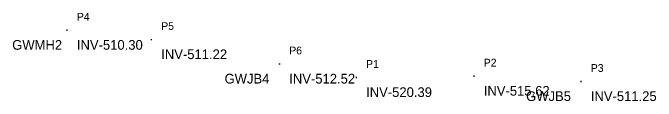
# Model space of a CAD drawing. Extents: x 1730979 to 1735363, y 649887 to 652110.
# Drawn here: x 1735032.4 to 1735362.8, y 649933.3 to 649978.8 of the extents above; entities that cross this region are included whole.
import ezdxf

# ---------------------------------------------------------------- set-up
doc = ezdxf.new("R2010")
doc.units = 0
for name, color, linetype in [('SURVEY - DRAINAGE - Storm Sewer - Points - Elevations', 7, 'Continuous'), ('SURVEY - DRAINAGE - Storm Sewer - Points - Locators', 7, 'Continuous'), ('SURVEY - DRAINAGE - Storm Sewer - Points - Numbers', 7, 'Continuous'), ('SURVEY - DRAINAGE - Storm Sewer Text', 7, 'Continuous')]:
    doc.layers.add(name, color=color, linetype=linetype)

msp = doc.modelspace()

# ---------------------------------------------------------------- linework, layer by layer
at = {"layer": 'SURVEY - DRAINAGE - Storm Sewer - Points - Locators'}
for p, q in [((1735060.58, 649969.75), (1735060.08, 649969.75)), ((1735060.33, 649969.5), (1735060.33, 649970)), ((1735060.33, 649969.75), (1735060.33, 649969.75)), ((1735060.33, 649969.75), (1735060.33, 649969.75)), ((1735103.88, 649964.94), (1735103.38, 649964.94)), ((1735103.63, 649964.69), (1735103.63, 649965.19)), ((1735103.63, 649964.94), (1735103.63, 649964.94)), ((1735103.63, 649964.94), (1735103.63, 649964.94)), ((1735169.63, 649952.36), (1735169.13, 649952.36)), ((1735169.38, 649952.11), (1735169.38, 649952.61)), ((1735169.38, 649952.36), (1735169.38, 649952.36)), ((1735169.38, 649952.36), (1735169.38, 649952.36)), ((1735209.09, 649945.43), (1735208.59, 649945.43)), ((1735208.84, 649945.18), (1735208.84, 649945.68)), ((1735208.84, 649945.43), (1735208.84, 649945.43)), ((1735208.84, 649945.43), (1735208.84, 649945.43)), ((1735269.53, 649946.11), (1735269.03, 649946.11)), ((1735269.28, 649945.86), (1735269.28, 649946.36)), ((1735269.28, 649946.11), (1735269.28, 649946.11)), ((1735269.28, 649946.11), (1735269.28, 649946.11)), ((1735324.49, 649943.36), (1735323.99, 649943.36)), ((1735324.24, 649943.11), (1735324.24, 649943.61)), ((1735324.24, 649943.36), (1735324.24, 649943.36)), ((1735324.24, 649943.36), (1735324.24, 649943.36))]:
    msp.add_line(p, q, dxfattribs=at)

# ---------------------------------------------------------------- texts
at = {"layer": 'SURVEY - DRAINAGE - Storm Sewer - Points - Elevations'}
for s, p in [('INV-510.30', (1735065.33, 649959.75)), ('INV-511.22', (1735108.63, 649954.94)), ('INV-512.52', (1735174.38, 649942.36)), ('INV-515.62', (1735274.28, 649936.11)), ('INV-520.39', (1735213.84, 649935.43)), ('INV-511.25', (1735329.24, 649933.36))]:
    msp.add_text(s, height=5, dxfattribs=at).set_placement(p)
at = {"layer": 'SURVEY - DRAINAGE - Storm Sewer - Points - Numbers'}
for s, p in [('P4', (1735065.33, 649974.75)), ('P5', (1735108.63, 649969.94)), ('P6', (1735174.38, 649957.36)), ('P1', (1735213.84, 649950.43)), ('P2', (1735274.28, 649951.11)), ('P3', (1735329.24, 649948.36))]:
    msp.add_text(s, height=4, dxfattribs=at).set_placement(p)
at = {"layer": 'SURVEY - DRAINAGE - Storm Sewer Text'}
for s, p in [('GWMH2', (1735032.11, 649959.75)), ('GWJB4', (1735141.16, 649942.36)), ('GWJB5', (1735296.02, 649933.36))]:
    msp.add_text(s, height=5, dxfattribs=at).set_placement(p)

doc.saveas('drawing.dxf')
